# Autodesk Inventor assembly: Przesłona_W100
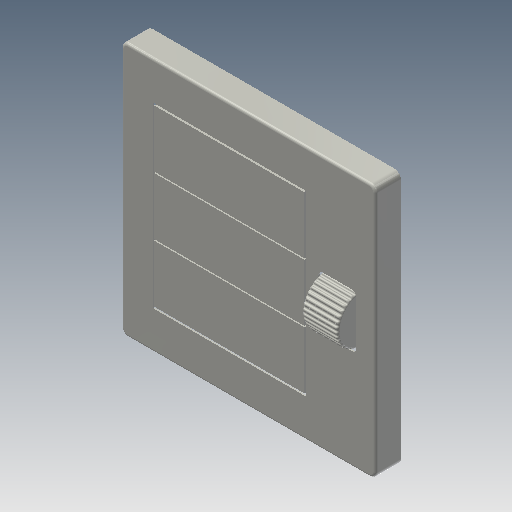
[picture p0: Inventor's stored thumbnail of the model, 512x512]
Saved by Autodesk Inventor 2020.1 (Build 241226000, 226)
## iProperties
Created: 2005-10
Part Number: Przesłona_W100
Document SubType Name: Assembly
Designer: F.Stasiak
Manager: www.cadconsulting.pl
Company: Fabian Stasiak CAD Consulting
Author: F.Stasiak
Subject: Zbiór ćwiczeń. Autodesk Inventor 2020. Kurs podstawowy
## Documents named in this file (5)
- C:\2020_Kurs_podstawowy\R6 Zespoły\Widok\Przesłona_W100.iam
- C:\2020_Kurs_podstawowy\R6 Zespoły\Widok\Ściana_W100.ipt
- C:\2020_Kurs_podstawowy\R6 Zespoły\Widok\Klapka_W100.ipt
- C:\2020_Kurs_podstawowy\R6 Zespoły\Widok\Kółko_W100.ipt
- C:\2020_Kurs_podstawowy\R6 Zespoły\Widok\Belka_W100.ipt
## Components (6 placed, 4 different names)
1. Ściana_W100:1 — Zestawiający:1, Równoległy:1, Zestawiający:2, Zestawiający:3, Równoległy:2, Równoległy:3, NAPĘD
2. Kółko_W100:1 — Równoległy:4, Zestawiający:4, Zestawiający:5, NAPĘD
3. Belka_W100:1 — Zestawiający:6, Zestawiający:7, Wstaw:1
4. Klapka_W100:1 — Zestawiający:1, Równoległy:1, Zestawiający:7
5. Klapka_W100:2 — Zestawiający:2, Równoległy:2, Zestawiający:6
6. Klapka_W100:3 — Zestawiający:3, Równoległy:3, Równoległy:4, Zestawiający:4, Zestawiający:5, Wstaw:1
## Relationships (13: Mate 7, Flush 4, Insert 1, Angle 1)
- Zestawiający:1 [Mate]: Ściana_W100:1 ↔ Klapka_W100:1
- Równoległy:1 [Flush]: Ściana_W100:1 ↔ Klapka_W100:1
- Zestawiający:2 [Mate]: Ściana_W100:1 ↔ Klapka_W100:2
- Zestawiający:3 [Mate]: Ściana_W100:1 ↔ Klapka_W100:3
- Równoległy:2 [Flush]: Ściana_W100:1 ↔ Klapka_W100:2
- Równoległy:3 [Flush]: Ściana_W100:1 ↔ Klapka_W100:3
- Równoległy:4 [Flush]: Kółko_W100:1 ↔ Klapka_W100:3
- Zestawiający:4 [Mate]: Kółko_W100:1 ↔ Klapka_W100:3
- Zestawiający:5 [Mate]: Kółko_W100:1 ↔ Klapka_W100:3
- Zestawiający:6 [Mate]: Belka_W100:1 ↔ Klapka_W100:2
- Zestawiający:7 [Mate]: Belka_W100:1 ↔ Klapka_W100:1
- Wstaw:1 [Insert]: Belka_W100:1 ↔ Klapka_W100:3
- NAPĘD [Angle]: Ściana_W100:1 ↔ Kółko_W100:1
